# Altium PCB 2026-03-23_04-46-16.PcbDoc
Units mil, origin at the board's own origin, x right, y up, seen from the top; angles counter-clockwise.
Board outline 4000 x 3500 mil, 4 copper layers (Top Layer, MidLayer1, MidLayer2, Bottom Layer); 141 components, 66 nets, 354 pads, 301 vias.
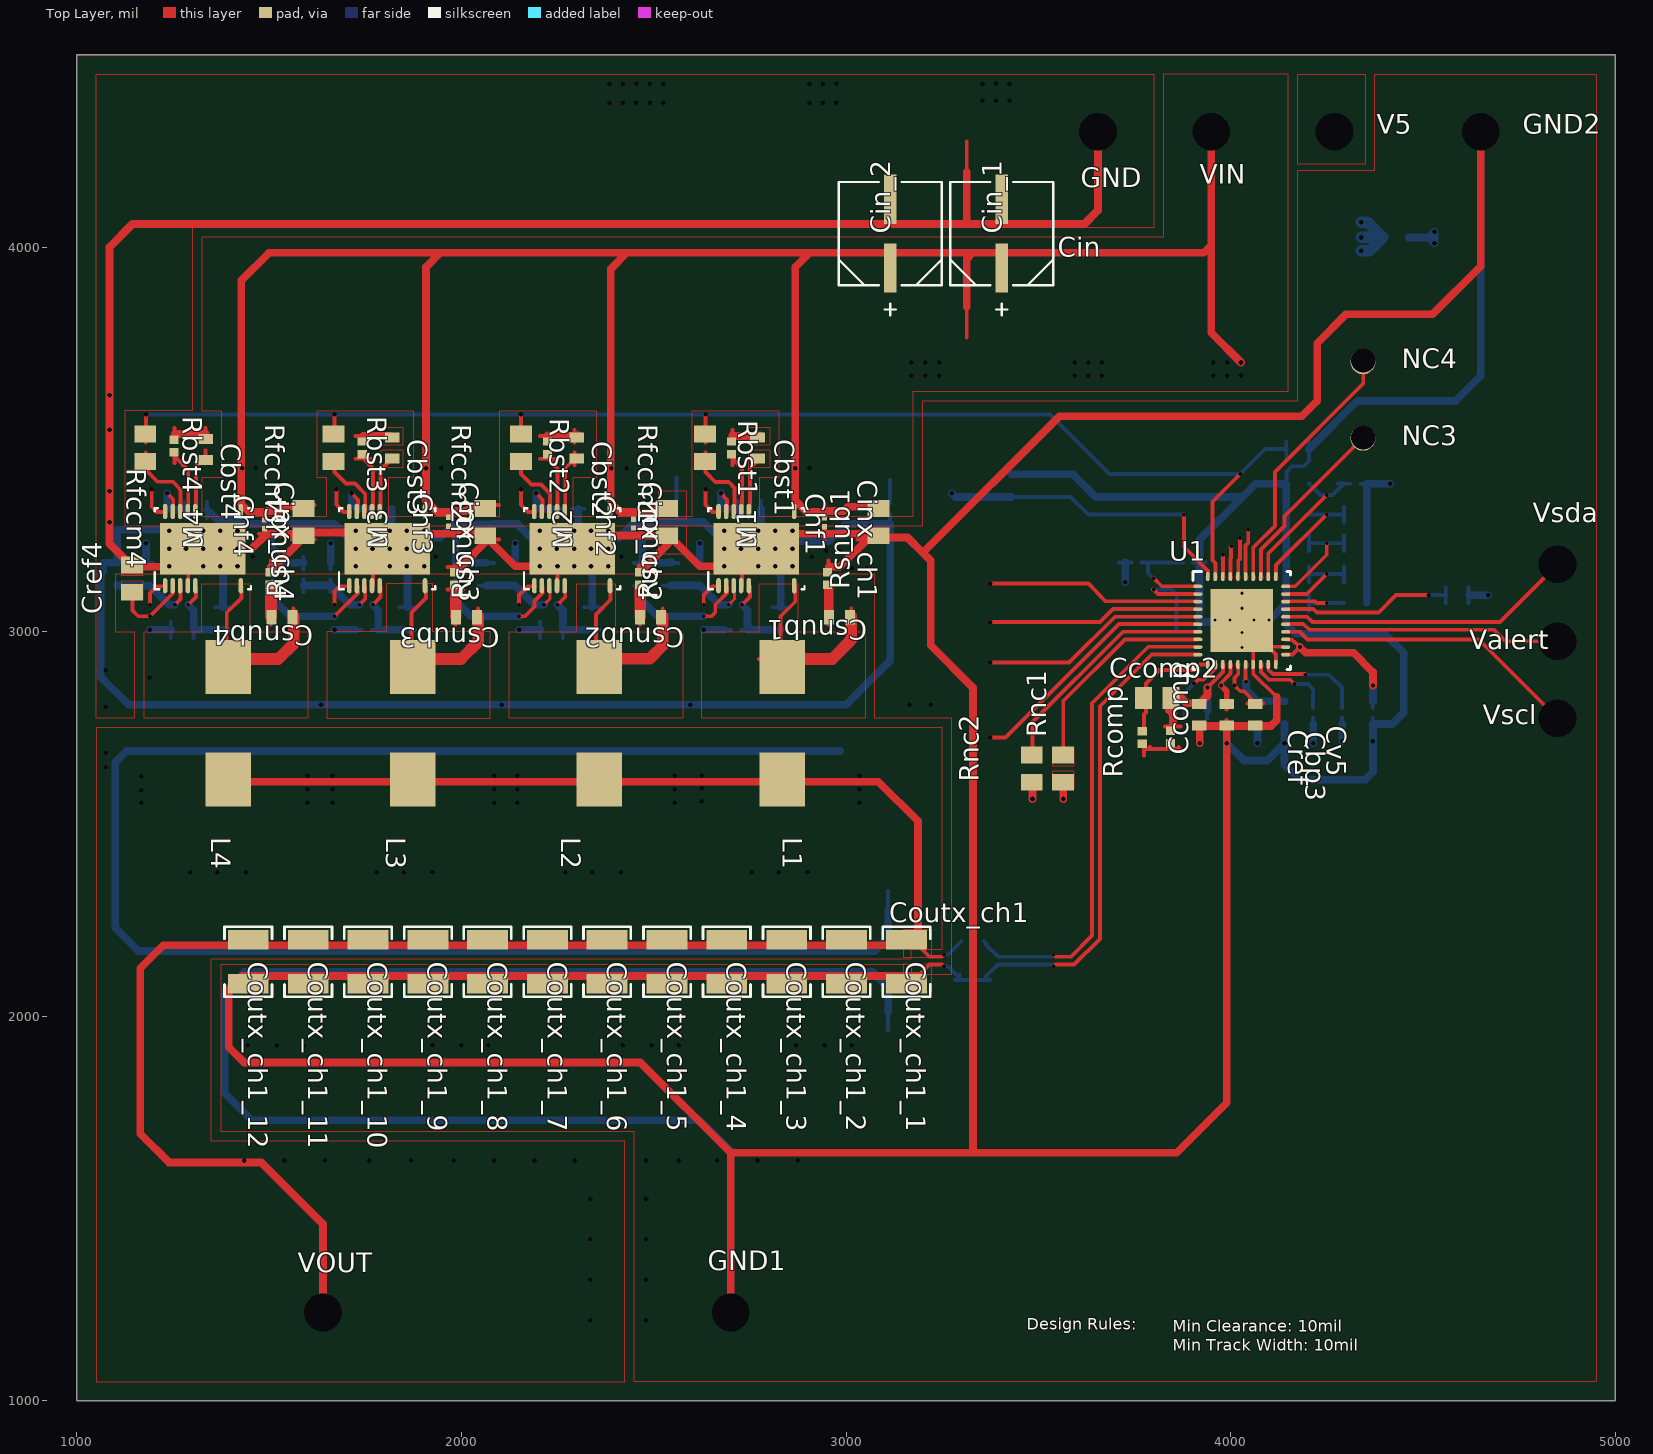
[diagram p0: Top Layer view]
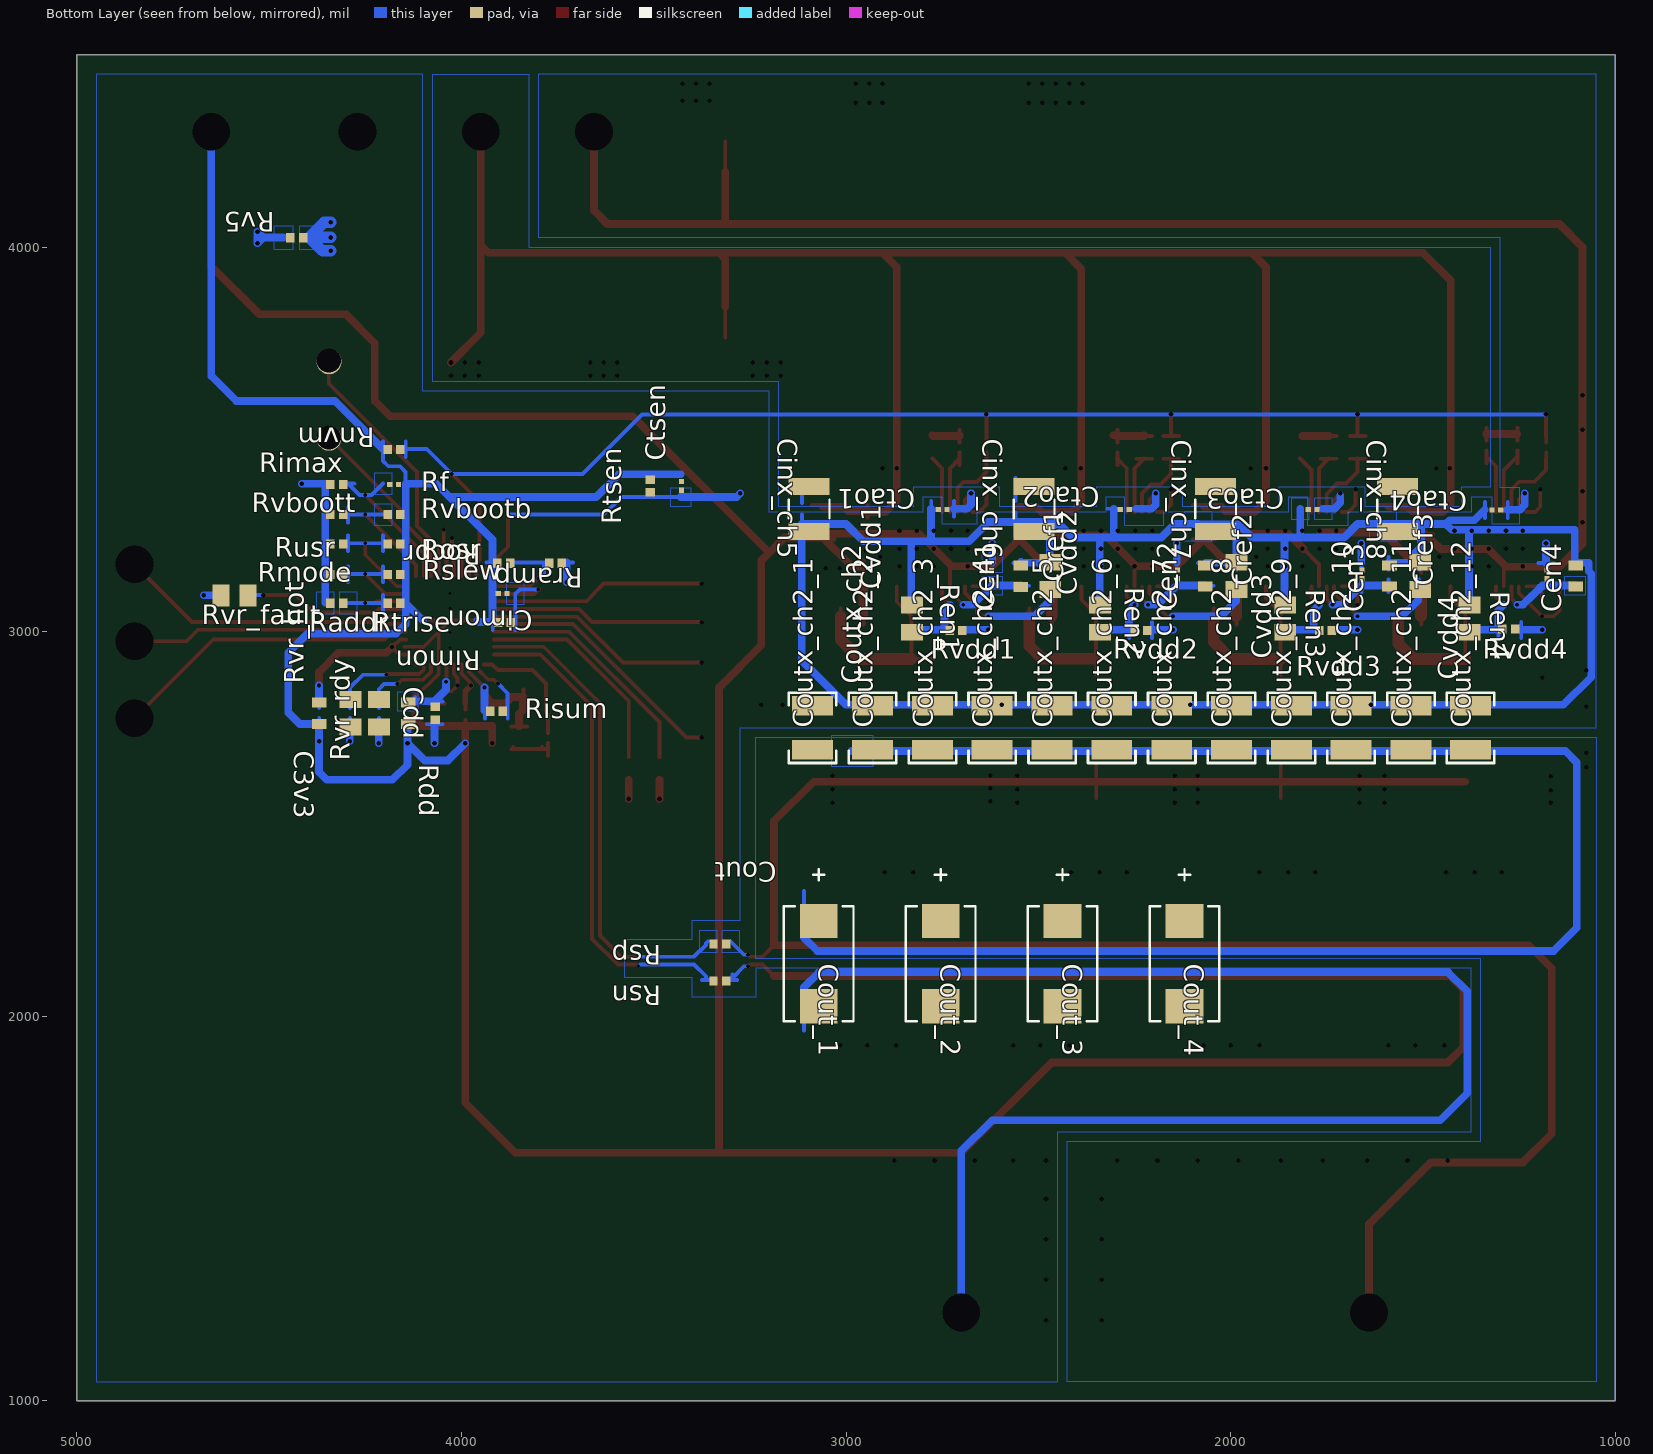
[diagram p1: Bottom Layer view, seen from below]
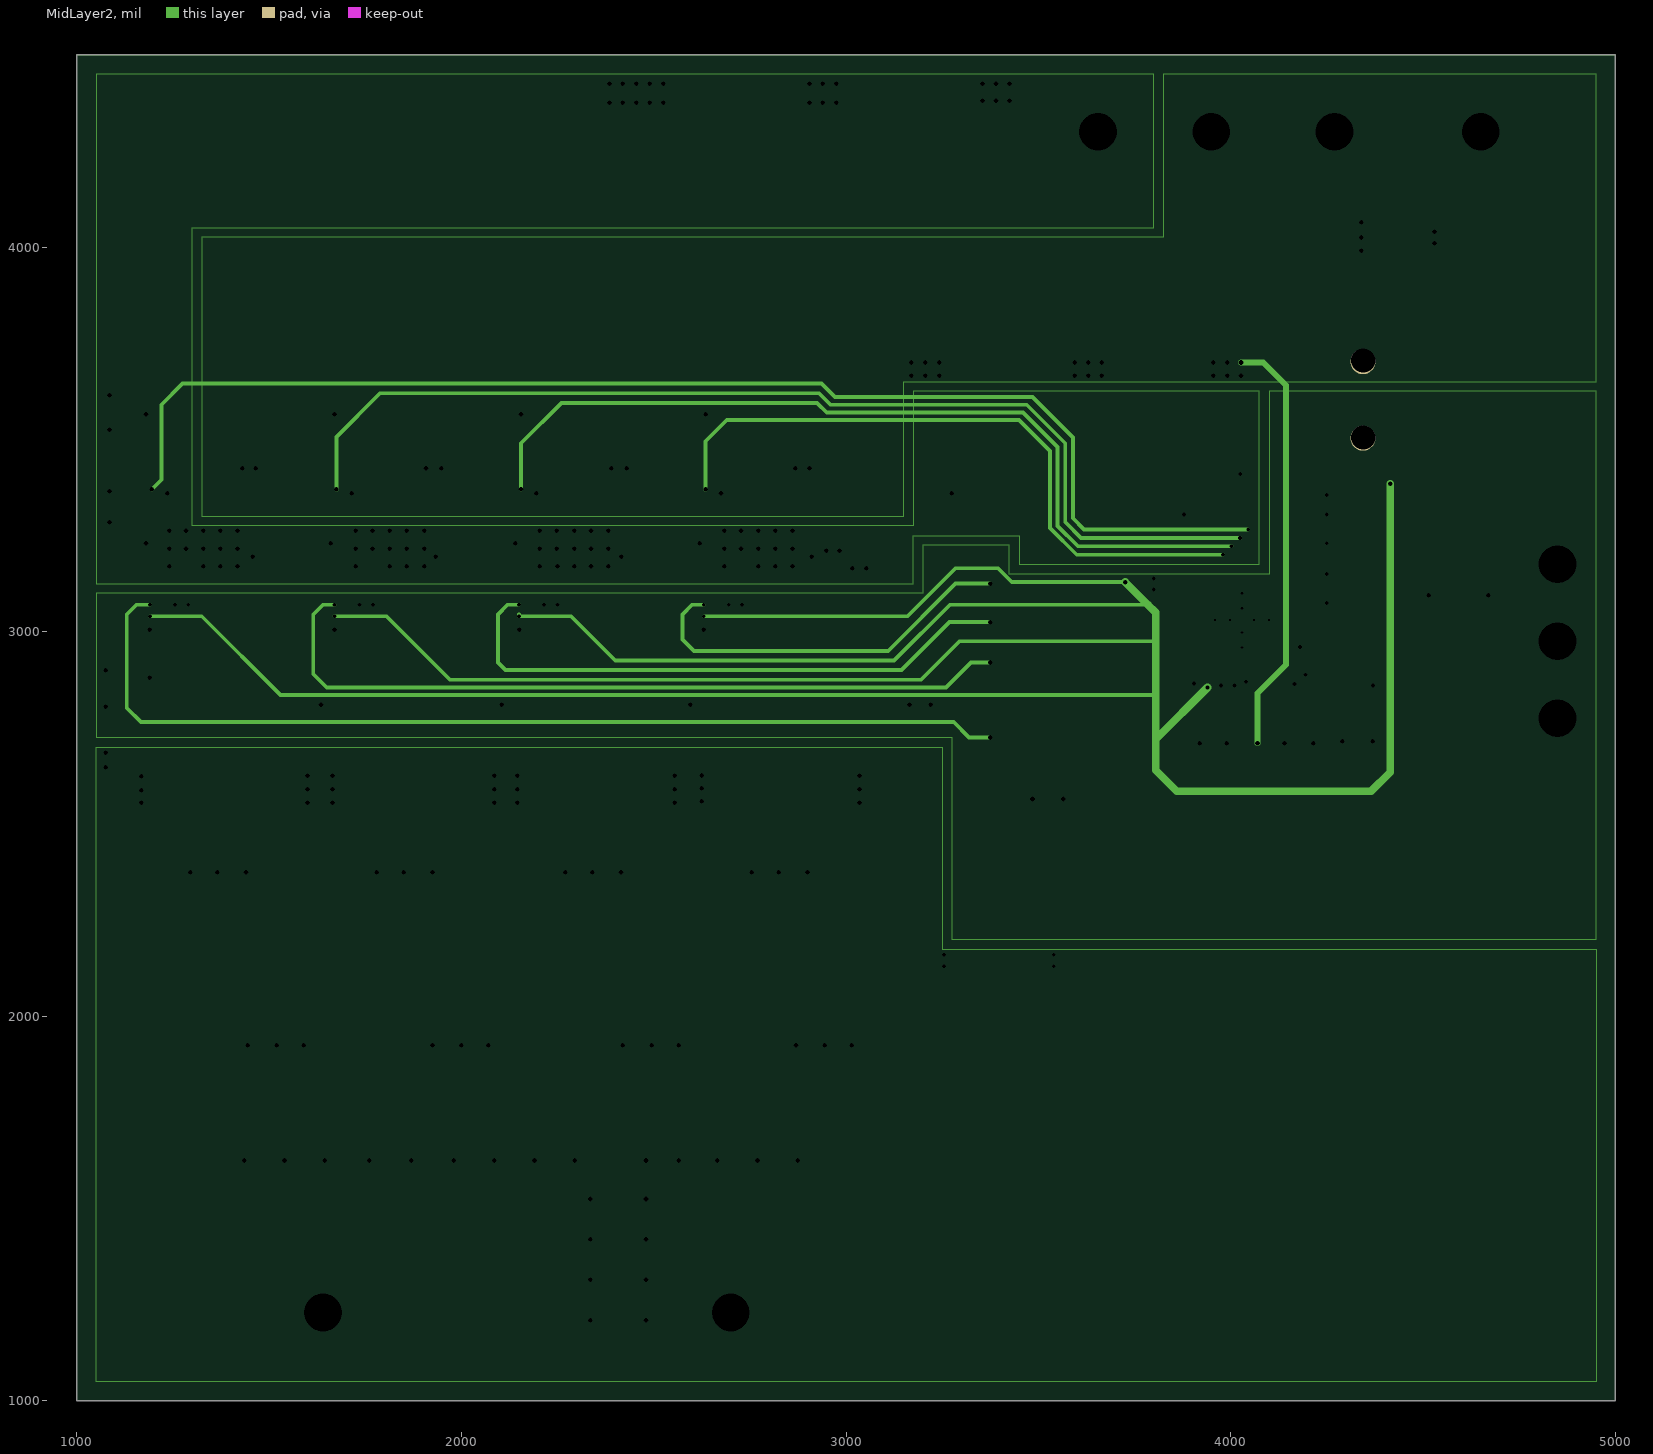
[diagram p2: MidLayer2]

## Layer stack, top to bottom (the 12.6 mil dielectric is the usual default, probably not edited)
Top Layer: signal copper 1.4
Dielectric: core 12.6, FR-4, Dk 4.8
MidLayer1: signal copper 1.4
Dielectric: prepreg 12.6, FR-4, Dk 4.8
MidLayer2: signal copper 1.4
Dielectric: core 12.6, FR-4, Dk 4.8
Bottom Layer: signal copper 1.4

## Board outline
1000,1000 5000,1000 5000,4500 1000,4500

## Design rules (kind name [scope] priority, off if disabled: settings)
PlaneConnect [All] p0: scope1count=1 scope1_0_kind=Board scope1_0_value=Board scope2count=1 scope2_0_kind=Board scope2_0_value=Board commentlength=0 planeconnectstyle=Direct reliefexpansion=20 reliefentries=4 reliefconductorwidth=10 reliefairgap=10
PlaneConnect [All] p1: planeconnectstyle=Direct reliefexpansion=20 reliefentries=4 reliefconductorwidth=10 reliefairgap=10
PolygonConnect [All] p0: scope1count=1 scope1_0_kind=Board scope1_0_value=Board scope2count=1 scope2_0_kind=Board scope2_0_value=Board commentlength=0 connectstyle=Direct reliefconductorwidth=10 reliefentries=4 polygonreliefangle="90 Angle"
PolygonConnect [All] p1: connectstyle=Direct reliefconductorwidth=10 reliefentries=4 polygonreliefangle="90 Angle"

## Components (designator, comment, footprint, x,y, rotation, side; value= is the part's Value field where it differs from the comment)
C3v3 "" 0603#1 4370,2788 r90 bottom
Cbp3 "" 0603#2 3990,2784 r270 top
Cbst1 "" 0603#2 2770,3478 r270 top
Cbst2 "" 0603#2 2300,3478 r270 top
Cbst3 "" 0603#2 1820,3478 r270 top
Cbst4 "" 0603#2 1335,3474 r270 top
Ccomp "" 0402#1 3844,2726 r90 top
Ccomp2 "" 0805#1 3809,2828 r0 top
Cdd "" 0603#1 4138,2788 r90 bottom
Cen1 "" 0603#1 2546,3144 r270 bottom
Cen2 "" 0603#1 2066,3145 r270 bottom
Cen3 "" 0603#1 1587,3145 r270 bottom
Cen4 "" 0603#1 1103,3145 r270 bottom
Chf1 "" 0201_033 2944,3284 r270 top
Chf2 "" 0201_033 2448,3281 r270 top
Chf3 "" 0201_033 1967,3286 r270 top
Chf4 "" 0201_033 1488,3279 r270 top
Cimon "" 0201 3893,3099 r180 bottom
Cin_1 "" CAPSMT_62_C10 3405,4035 r90 top
Cin_2 "" CAPSMT_62_C10 3115,4035 r90 top
Cinx_ch1 "" 0805#1 3084,3285 r270 top
Cinx_ch2 "" 0805#1 2535,3285 r270 top
Cinx_ch3 "" 0805#1 2062,3285 r270 top
Cinx_ch4 "" 0805#1 1590,3285 r270 top
Cinx_ch5 "" 1210_280 3096,3319 r90 bottom
Cinx_ch6 "" 1210_280 2511,3319 r90 bottom
Cinx_ch7 "" 1210_280 2039,3319 r90 bottom
Cinx_ch8 "" 1210_280 1566,3319 r90 bottom
Cout_1 "" 7343-20 3071,2137 r90 bottom
Cout_2 "" 7343-20 2754,2137 r90 bottom
Cout_3 "" 7343-20 2437,2137 r90 bottom
Cout_4 "" 7343-20 2120,2137 r90 bottom
Coutx_ch1_1 "" 1210_270#1 3157,2142 r270 top
Coutx_ch1_2 "" 1210_270#1 3001,2142 r270 top
Coutx_ch1_3 "" 1210_270#1 2846,2142 r270 top
Coutx_ch1_4 "" 1210_270#1 2690,2142 r270 top
Coutx_ch1_5 "" 1210_270#1 2535,2142 r270 top
Coutx_ch1_6 "" 1210_270#1 2379,2142 r270 top
Coutx_ch1_7 "" 1210_270#1 2224,2142 r270 top
Coutx_ch1_8 "" 1210_270#1 2068,2142 r270 top
Coutx_ch1_9 "" 1210_270#1 1913,2142 r270 top
Coutx_ch1_10 "" 1210_270#1 1757,2142 r270 top
Coutx_ch1_11 "" 1210_270#1 1602,2142 r270 top
Coutx_ch1_12 "" 1210_270#1 1446,2142 r270 top
Coutx_ch2_1 "" 1210_270#2 3087,2750 r270 bottom
Coutx_ch2_2 "" 1210_270#2 2931,2750 r270 bottom
Coutx_ch2_3 "" 1210_270#2 2775,2750 r270 bottom
Coutx_ch2_4 "" 1210_270#2 2620,2750 r270 bottom
Coutx_ch2_5 "" 1210_270#2 2464,2750 r270 bottom
Coutx_ch2_6 "" 1210_270#2 2309,2750 r270 bottom
Coutx_ch2_7 "" 1210_270#2 2153,2750 r270 bottom
Coutx_ch2_8 "" 1210_270#2 1998,2750 r270 bottom
Coutx_ch2_9 "" 1210_270#2 1842,2750 r270 bottom
Coutx_ch2_10 "" 1210_270#2 1687,2750 r270 bottom
Coutx_ch2_11 "" 1210_270#2 1531,2750 r270 bottom
Coutx_ch2_12 "" 1210_270#2 1376,2750 r270 bottom
Cref "" 0603#2 3918,2784 r270 top
Cref1 "" 0805#2 2469,3145 r270 bottom
Cref2 "" 0805#2 1985,3145 r270 bottom
Cref3 "" 0805#2 1507,3145 r270 bottom
Cref4 "" 0805#1 1144,3138 r90 top
Csnub1 "" 0603#2 2983,3038 r180 top
Csnub2 "" 0603#2 2492,3038 r180 top
Csnub3 "" 0603#2 2013,3038 r180 top
Csnub4 "" 0603#2 1534,3038 r180 top
Ctao1 "" 0201 2749,3318 r180 bottom
Ctao2 "" 0201 2275,3318 r180 bottom
Ctao3 "" 0201 1787,3318 r180 bottom
Ctao4 "" 0201 1309,3316 r180 bottom
Ctsen "" 0201 3428,3379 r270 bottom
Cv5 "" 0603#2 4064,2784 r270 top
Cvdd1 "" 0805#2 2828,3034 r270 bottom
Cvdd2 "" 0805#2 2340,3034 r270 bottom
Cvdd3 "" 0805#2 1858,3034 r270 bottom
Cvdd4 "" 0805#2 1379,3034 r270 bottom
GND "" TP-1502 3655,4298 r0 top
GND1 "" TP-1502 2698,1228 r0 top
GND2 "" TP-1502 4649,4298 r0 top
L1 "" WE-HCM_1088 2834,2762 r270 top
L2 "" WE-HCM_1088 2359,2762 r270 top
L3 "" WE-HCM_1088 1874,2762 r270 top
L4 "" WE-HCM_1088 1394,2762 r270 top
M1 "" DQP0012A 2767,3216 r90 top
M2 "" DQP0012A 2288,3216 r90 top
M3 "" DQP0012A 1807,3216 r90 top
M4 "" DQP0012A 1328,3216 r90 top
NC3 "" TP-5012 4344,3503 r0 top
NC4 "" TP-5012 4344,3702 r0 top
Raddr "" 0402#2 4324,3074 r0 bottom
Rbst1 "" 0402#1 2702,3478 r270 top
Rbst2 "" 0402#1 2224,3478 r270 top
Rbst3 "" 0402#1 1742,3478 r270 top
Rbst4 "" 0402#1 1253,3483 r270 top
Rcomp "" 0402#1 3770,2725 r90 top
Rdd "" 0402#2 4068,2788 r90 bottom
Ren1 "" 0201 2622,3147 r90 bottom
Ren2 "" 0201 2138,3149 r90 bottom
Ren3 "" 0201 1659,3149 r90 bottom
Ren4 "" 0201 1178,3149 r90 bottom
Rf "" 0201 4175,3383 r0 bottom
Rfccm1 "" 0805#1 2633,3478 r270 top
Rfccm2 "" 0805#1 2155,3478 r270 top
Rfccm3 "" 0805#1 1668,3478 r270 top
Rfccm4 "" 0805#1 1178,3478 r270 top
Rimax "" 0402#2 4324,3383 r0 bottom
Rimon "" 0402#2 3888,3024 r180 bottom
Risum "" 0402#2 3909,2793 r0 bottom
Rmode "" 0402#2 4324,3149 r0 bottom
Rnc1 "" 0805#1 3564,2644 r90 top
Rnc2 "" 0805#1 3483,2644 r90 top
Rnvm "" 0402#2 4175,3474 r180 bottom
Rocpr "" 0402#2 3890,3178 r180 bottom
Rosr "" 0402#2 4175,3228 r0 bottom
Rramp "" 0402#2 3755,3178 r180 bottom
Rslew "" 0402#2 4175,3149 r0 bottom
Rsn "" 0402#2 3328,2092 r180 bottom
Rsnub1 "" 0402#1 2952,3138 r90 top
Rsnub2 "" 0402#1 2464,3138 r90 top
Rsnub3 "" 0402#1 1983,3138 r90 top
Rsnub4 "" 0402#1 1503,3138 r90 top
Rsp "" 0402#2 3328,2188 r180 bottom
Rtrise "" 0402#2 4175,3074 r0 bottom
Rtsen "" 0402#2 3509,3379 r270 bottom
Rusr "" 0402#2 4324,3228 r0 bottom
Rv5 "" 0402#2 4428,4024 r180 bottom
Rvbootb "" 0402#2 4175,3305 r0 bottom
Rvboott "" 0402#2 4324,3305 r0 bottom
Rvdd1 "" 0402#2 2714,3003 r0 bottom
Rvdd2 "" 0402#2 2233,3003 r0 bottom
Rvdd3 "" 0402#2 1753,3003 r0 bottom
Rvdd4 "" 0402#2 1277,3007 r0 bottom
Rvr_fault "" 0805#2 4590,3094 r0 bottom
Rvr_hot "" 0805#2 4288,2788 r270 bottom
Rvr_rdy "" 0805#2 4214,2788 r270 bottom
U1 "" RTA0040B 4029,3029 r0 top
V5 "" TP-1502 4269,4298 r0 top
Valert "" TP-1502 4849,2974 r0 top
VIN "" TP-1502 3948,4298 r0 top
VOUT "" TP-1502 1638,1228 r0 top
Vscl "" TP-1502 4849,2775 r0 top
Vsda "" TP-1502 4849,3175 r0 top

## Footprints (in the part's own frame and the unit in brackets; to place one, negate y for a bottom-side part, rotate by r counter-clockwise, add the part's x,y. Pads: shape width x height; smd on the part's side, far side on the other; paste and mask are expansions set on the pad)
0201 [mil]
  rect 14x13 smd: 1(11.5,0) 2(-11.5,0)
0201_033 [mil]
  rect 14x13 smd: 1(-11.5,0) 2(11.5,0)
0402#1 [mil]
  rect 22x24 smd: 1(-16.5,0) 2(16.5,0)
0402#2 [mil]
  rect 22x24 smd: 1(16.5,0) 2(-16.5,0)
0603#1 [mil]
  rect 26x38 smd: 1(27.5,0) 2(-27.5,0)
0603#2 [mil]
  rect 26x38 smd: 1(-27.5,0) 2(27.5,0)
0805#1 [mil]
  rect 44x57 smd: 1(-35.5,0) 2(35.5,0)
0805#2 [mil]
  rect 44x57 smd: 1(35.5,0) 2(-35.5,0)
1210_270#1 [mm]
  rect 1.3x2.7 smd: 1(-1.45,0) 2(1.45,0)
  silkscreen extent -2.32,-1.57 2.32,1.57
1210_270#2 [mm]
  rect 1.3x2.7 smd: 1(1.45,0) 2(-1.45,0)
  silkscreen extent -2.32,-1.57 2.32,1.57
1210_280 [mil]
  rect 44x106 smd: 1(59,0) 2(-59,0)
  silkscreen extent -24,-53 24,53
7343-20 [mil]
  rect 89x98 smd: 1(111,0) 2(-111,0)
  silkscreen extent -150,-91 246,91
CAPSMT_62_C10 [mil]
  rect 128x32 smd: 1(-89.5,0) 2(89.5,0)
  silkscreen extent -212,-134 134,134
DQP0012A [mm]
  oval 1x0.3 smd: 1(-2.45,2.501) 2(-2.45,2.001) 3(-2.45,1.5) 4(-2.45,1) 5(-2.45,0.5) 6(-2.45,-2.501) 7(2.45,-2.501) 8(2.45,0.5) 9(2.45,1) 10(2.45,1.5) 11(2.45,2.001) 12(2.45,2.501)
  rect 3.4x5.639 smd: 13(0,0)
  silkscreen extent -2.68,-3.17 2.68,3.17
RTA0040B [mm]
  oval 0.6x0.23 smd: 1(-2.9,2.25) 2(-2.9,1.75) 3(-2.9,1.25) 4(-2.9,0.75) 5(-2.9,0.25) 6(-2.9,-0.25) 7(-2.9,-0.75) 8(-2.9,-1.25) 9(-2.9,-1.75) 10(-2.9,-2.25) 21(2.9,-2.25) 22(2.9,-1.75) 23(2.9,-1.25) 24(2.9,-0.75) 25(2.9,-0.25) 26(2.9,0.25) 27(2.9,0.75) 28(2.9,1.25) 29(2.9,1.75) 30(2.9,2.25)
  oval 0.23x0.6 smd: 11(-2.25,-2.9) 12(-1.75,-2.9) 13(-1.25,-2.9) 14(-0.75,-2.9) 15(-0.25,-2.9) 16(0.25,-2.9) 17(0.75,-2.9) 18(1.25,-2.9) 19(1.75,-2.9) 20(2.25,-2.9) 31(2.25,2.9) 32(1.75,2.9) 33(1.25,2.9) 34(0.75,2.9) 35(0.25,2.9) 36(-0.25,2.9) 37(-0.75,2.9) 38(-1.25,2.9) 39(-1.75,2.9) 40(-2.25,2.9)
  rect 4.15x4.15 smd: 41(0,0)
  silkscreen extent -3.22,-3.22 3.22,3.22
TP-1502 [mil]
  round 65 hole 32: 1(0,0)
TP-5012 [mil]
  round 65 hole 32: 1(0,0)
WE-HCM_1088 [mm]
  rect 3.56x3 smd: 1(-3.71,0) 2(3.71,0)

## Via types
v1: diameter 0, hole 12, Top Layer to Bottom Layer, 240 vias
v2: diameter 0, hole 10, Top Layer to Bottom Layer, 42 vias
v3: diameter 0, hole 98, Top Layer to Bottom Layer, 9 vias
v4: diameter 0, hole 8, Top Layer to Bottom Layer, 8 vias
v5: diameter 0, hole 63, Top Layer to Bottom Layer, 2 vias

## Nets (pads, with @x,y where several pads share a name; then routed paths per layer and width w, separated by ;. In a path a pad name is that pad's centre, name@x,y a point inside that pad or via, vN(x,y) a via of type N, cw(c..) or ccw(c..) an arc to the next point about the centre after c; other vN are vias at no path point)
0: C3v3.2 Cbp3.2 Cdd.2 Cen1.2 Cen2.2 Cen3.2 Cen4.2 Chf1.2 Chf2.2 Chf3.2 Chf4.2 Cimon.2 Cin_1.2 Cin_2.2 Cinx_ch1.2 Cinx_ch2.2 Cinx_ch3.2 Cinx_ch4.2 Cinx_ch5.2 Cinx_ch6.2 Cinx_ch7.2 Cinx_ch8.2 Cout_1.2 Cout_2.2 Cout_3.2 Cout_4.2 Coutx_ch1_1.2 Coutx_ch1_2.2 Coutx_ch1_3.2 Coutx_ch1_4.2 Coutx_ch1_5.2 Coutx_ch1_6.2 Coutx_ch1_7.2 Coutx_ch1_8.2 Coutx_ch1_9.2 Coutx_ch1_10.2 Coutx_ch1_11.2 Coutx_ch1_12.2 Coutx_ch2_1.2 Coutx_ch2_2.2 Coutx_ch2_3.2 Coutx_ch2_4.2 Coutx_ch2_5.2 Coutx_ch2_6.2 Coutx_ch2_7.2 Coutx_ch2_8.2 Coutx_ch2_9.2 Coutx_ch2_10.2 Coutx_ch2_11.2 Coutx_ch2_12.2 Cref1.2 Cref2.2 Cref3.2 Cref4.2 Cref.2 Ctao1.2 Ctao2.2 Ctao3.2 Ctao4.2 Ctsen.2 Cv5.2 Cvdd1.2 Cvdd2.2 Cvdd3.2 Cvdd4.2 GND1.1 GND2.1 GND.1 M1.4 M1.13 M2.4 M2.13 M3.4 M3.13 M4.4 M4.13 Rf.2 Rimon.2 Rnvm.2 Rocpr.2 Rosr.2 Rslew.2 Rsn.1 Rsnub1.2 Rsnub2.2 Rsnub3.2 Rsnub4.2 Rtrise.2 Rtsen.2 Rvbootb.2 U1.17 U1.20 U1.22 U1.41 | length 34184.2
  Top Layer w10: M4.4@1290,3118 M4.13@1290,3175 ; 1474,3254.5 1515,3254.5 ; Rsnub4.2@1504.5,3152 1504.5,3185 ; 1560,3239.5 Cinx_ch4.2@1618,3239.5 ; M3.4@1770,3118 1770,3175 M3.13@1810,3215 ; 1959,3254.5 2000,3254.5 ; 1964,3168.5 2005,3168.5 ; Cinx_ch3.2@2040,3239.5 2098,3239.5 ; M2.4@2250,3118 M2.13@2250,3158 ; 2439,3249.5 2480,3249.5 ; M1.4@2730,3118 M1.13@2730,3175 ; 2944.5,3238 Chf1.2@2944.5,3271 ; Rsnub1.2@2954.5,3152 2954.5,3185 ; 3030,3239.5 Cinx_ch1.2@3088,3239.5 ; Coutx_ch1_1.2@3187,2105 3217,2135 3250,2135 v2(3255,2130) ; 3314,4116 3314,4275 ; U1.41@3955,3029.5 U1.41@4104,3029.5 ; 3989.5,2738 3989.5,2771 ; U1.41@4030,3030 U1.41@4059,3000 ; 4044,2754.5 4085,2754.5 ; U1.20@4118,2915 4118,2941 U1.41@4098,2961 ; 4120,2830 4059,2890 4059,2915 U1.41@4059,3000 ; U1.22@4148,2961 U1.41@4098,2961 ; U1.41@4059,3000 U1.41@4098,2961
  Top Layer w20: 1505,3169 1514,3169 Cinx_ch4.2@1590,3245 ; M3.13@1767,3258 1603,3258 Cinx_ch4.2@1590,3245 ; M3.13@1810,3215 1850,3255 1980,3255 2054,3255 Cinx_ch3.2@2070,3240 ; 1985,3169 1999,3169 Cinx_ch3.2@2070,3240 ; 2465,3169 2479,3169 Cinx_ch2.2@2550,3240 ; v3(2700,1230) 2700,1645 ; 2955,3169 2984,3169 Cinx_ch1.2@3060,3245 ; Coutx_ch1_1.2@3187,2105 1430,2105 1395,2070 1395,1920 1435,1880 2465,1880 2700,1645 ; 3314,4195 3314,4060 ; v3(3655,4300) 3655,4095 3620,4060 3315,4060 3314,4060 ; v1(3920,2710) 3920,2755 Cbp3.2@3990,2755 ; 4120,2830 4120,2770 4105,2755 4065,2755 Cbp3.2@3990,2755 ; v3(4650,4300) 4650,3950 4525,3825 4300,3825 4225,3750 4225,3600 4185,3560 3555,3560 3200,3205 ; Cinx_ch4.2@1590,3245 1579,3255 1495,3255 1454,3215 1330,3215 1290,3175 1284,3169 1145,3169 1085,3229 v1(1085,3615) 1085,4000 1145,4060 3314,4060 ; Cinx_ch3.2@2070,3240 2140,3170 2245,3170 2325,3250 2460,3250 2539,3250 Cinx_ch2.2@2550,3240 ; Cinx_ch2.2@2550,3240 2620,3170 2725,3170 2730,3175 2810,3255 2945,3255 3049,3255 Cinx_ch1.2@3060,3245 ; 2700,1645 3330,1645 ; Cinx_ch1.2@3060,3245 3160,3245 3200,3205 ; 3200,3205 3220,3185 3220,2965 3330,2855 3330,1645 ; 3330,1645 3860,1645 3990,1775 v1(3990,2710) Cbp3.2@3990,2755
  Bottom Layer w10: 1338.5,3296 1338.5,3337 ; Cvdd4.2@1359,3063.5 Cvdd4.2@1400,3063.5 ; Cref3.2@1509.5,3162 Cref3.2@1509.5,3195 ; Cen3.2@1589.5,3162 1589.5,3195 ; Cvdd3.2@1839,3063.5 Cvdd3.2@1880,3063.5 ; Cref2.2@1984.5,3162 Cref2.2@1984.5,3195 ; 2044,3178.5 2085,3178.5 ; Ctao2.2@2287,3319.5 2320,3319.5 ; Cvdd2.2@2319,3063.5 Cvdd2.2@2360,3063.5 ; Cref1.2@2449,3178.5 Cref1.2@2490,3178.5 ; 2524,3178.5 2565,3178.5 ; Cinx_ch6.2@2559,3249 2559,3310 ; 2778.5,3299 2778.5,3340 ; Cvdd1.2@2809,3063.5 Cvdd1.2@2850,3063.5 ; 3109,1963 Cout_1.2@3109,2059 ; Cinx_ch5.2@3114,3244 3114,3305 ; v2(3255,2130) 3265,2130 3295,2100 ; 3283,2094.5 Rsn.1@3316,2094.5 ; 3295,2109 3295,2100 ; 3300,2095 3295,2100 ; 3489,3408.5 3530,3408.5 ; Rocpr.2@3902,3179.5 3935,3179.5 ; 3918.5,3004 3918.5,3045 ; 3919,3050 3919,3100 ; 4144.5,3054 4144.5,3095 ; 4144.5,3129 4144.5,3170 ; 4144.5,3209 4144.5,3250 ; 4145,3385 4145,3415 4160,3430 4190,3430 4204,3444 4204,3475 ; 4203.5,3454 4203.5,3495 ; 4369.5,2743 4369.5,2776
  Bottom Layer w20: 1339,3317 1367,3290 1430,3290 1440,3280 ; Cvdd4.2@1380,3064 1380,3258 ; Cen3.2@1590,3179 1520,3179 1520,3205 1505,3220 1505,3280 ; 1819,3320 1819,3245 ; Cvdd3.2@1860,3064 1860,3245 ; Cen2.2@2065,3179 1985,3179 1985,3274 1980,3279 ; 2304,3320 2304,3245 2305,3245 ; Cvdd2.2@2340,3064 2340,3245 ; Cen1.2@2544,3180 Cen1.2@2545,3181 ; Cen1.2@2545,3179 2470,3179 2470,3265 2450,3285 ; v3(2700,1230) 2700,1650 2620,1730 1455,1730 1385,1800 1385,2065 1435,2115 3070,2115 3110,2075 Cout_1.2@3110,2011 ; 2779,3320 2779,3235 2780,3235 ; Cvdd1.2@2830,3064 2830,3235 ; 3430,3409 3510,3409 3590,3409 3650,3350 4030,3350 ; v4(3959,3030) 3954,3025 3919,3025 3919,3050 3919,3115 3919,3180 3919,3239 4030,3350 ; v1(3990,2710) 4035,2665 4095,2665 v1(4140,2710) ; v4(4100,3030) 4145,3074 ; Cdd.2@4140,2760 v1(4140,2710) ; 4204,3475 4329,3600 4585,3600 4650,3665 v3(4650,4300) ; 1440,3280 1425,3265 1105,3265 1105,3179 1069,3179 1069,3157 1062,3150 1062,2882 1135,2810 2985,2810 3000,2810 3115,2925 3115,3280 3000,3280 2955,3235 2830,3235 ; 1440,3280 1505,3280 ; 1505,3280 1605,3280 1670,3280 1705,3245 1819,3245 ; 1819,3245 1860,3245 ; 1860,3245 1945,3245 1980,3279 ; 1980,3279 2084,3279 2085,3280 2145,3280 2180,3245 2305,3245 ; 2305,3245 2340,3245 ; 2340,3245 2410,3245 2450,3285 ; 2450,3285 2560,3285 2630,3285 2680,3235 2780,3235 ; 2780,3235 2830,3235 ; 4030,3350 4065,3385 4145,3385 4145,3305 4145,3230 4145,3150 4145,3075 4145,3074 ; v1(4140,2710) 4140,2654 4180,2615 4350,2615 4370,2635 4370,2760 4420,2760 4450,2790 4450,2945 4400,2995 4170,2995 4145,3019 4145,3074
  other v1: 2480,1210 2480,1315 2480,1420 2480,1525 2480,1625 2565,1625 2665,1625 2770,1625 2875,1625 1445,1925 1520,1925 1590,1925 1925,1925 2000,1925 2070,1925 2420,1925 2495,1925 2565,1925 2870,1925 2945,1925 3015,1925 4370,2715 1075,2805 1635,2810 2105,2810 2595,2810 3165,2810 3220,2810 1190,2880 1075,2900 3016,3165 3053,3165 1240,3170 1329,3170 1373,3170 1418,3170 1725,3170 1814,3170 1858,3170 1903,3170 2204,3170 2250,3170 2293,3170 2337,3170 2382,3170 2683,3170 2772,3170 2816,3170 2861,3170 1458,3195 1933,3195 2416,3195 2911,3195 2949,3210 2983,3210 1240,3216 1284,3216 1329,3216 1373,3216 1418,3216 1725,3216 1769,3216 1814,3216 1858,3216 1903,3216 2204,3216 2248,3216 2293,3216 2337,3216 2382,3216 2683,3216 2727,3216 2772,3216 2816,3216 2861,3216 1240,3262 1284,3262 1329,3262 1373,3262 1418,3262 1725,3262 1769,3262 1814,3262 1858,3262 1903,3262 2204,3262 2248,3262 2293,3262 2337,3262 2382,3262 2683,3262 2727,3262 2772,3262 2816,3262 2861,3262 1085,3285 1085,3365 1085,3525 2385,4375 2420,4375 2455,4375 2490,4375 2525,4375 2905,4375 2940,4375 2975,4375 3355,4380 3390,4380 3425,4380 2385,4425 2420,4425 2455,4425 2490,4425 2525,4425 2905,4425 2940,4425 2975,4425 3355,4425 3390,4425 3425,4425
  other v4: 4030,2959 4030,2998 3998,3030 4061,3030 4030,3061 4030,3100
1: Chf1.1 Chf2.1 Chf3.1 Chf4.1 Cin_1.1 Cin_2.1 Cinx_ch1.1 Cinx_ch2.1 Cinx_ch3.1 Cinx_ch4.1 Cinx_ch5.1 Cinx_ch6.1 Cinx_ch7.1 Cinx_ch8.1 M1.7 M2.7 M3.7 M4.7 Rdd.2 VIN.1 | length 8456.4
  Top Layer w10: 1474,3313.5 1515,3313.5 ; 1560,3329.5 Cinx_ch4.1@1618,3329.5 ; 1959,3313.5 2000,3313.5 ; Cinx_ch3.1@2040,3329.5 2098,3329.5 ; 2439,3308.5 2480,3308.5 ; Chf1.1@2944.5,3297 2944.5,3330 ; 3030,3329.5 Cinx_ch1.1@3088,3329.5 ; 3314,3765 3314,3924
  Top Layer w20: Cinx_ch4.1@1590,3325 1540,3325 1529,3314 1495,3314 1491,3311 1448,3311 1428,3331 1428,3913 1500,3985 1945,3985 ; Cinx_ch3.1@2070,3325 2025,3325 2014,3314 1980,3314 1976,3311 1938,3311 1908,3341 1908,3948 1945,3985 ; Cinx_ch2.1@2550,3325 2505,3325 2489,3309 2460,3309 2458,3311 2413,3311 2388,3336 2388,3943 2430,3985 ; Cinx_ch1.1@3060,3325 3005,3325 2994,3314 2945,3314 2941,3311 2898,3311 2868,3341 2868,3948 2905,3985 ; 3314,3845 3314,3969 3330,3985 ; v3(3950,4300) 3950,4005 ; v1(4027,3700) 3950,3777 3950,4005 ; 1945,3985 2430,3985 ; 2430,3985 2905,3985 ; 2905,3985 3330,3985 ; 3330,3985 3930,3985 3950,4005
  MidLayer2 w15: v1(4027,3700) 4085,3700 4144,3641 4144,2914 4070,2840 v1(4070,2710)
  Bottom Layer w10: 2559,3339 2559,3400 ; 3114,3334 Cinx_ch5.1@3114,3395 ; 4049,2759.5 4090,2759.5
  Bottom Layer w20: v1(4070,2710) 4070,2760
  other v1: 1430,3425 1465,3425 1908,3425 1948,3425 2390,3425 2430,3425 2868,3425 2905,3425 3170,3665 3206,3665 3242,3665 3595,3665 3630,3665 3665,3665 3955,3665 3991,3665 4027,3665 3170,3700 3206,3700 3242,3700 3595,3700 3630,3700 3665,3700 3955,3700 3991,3700
2: Rocpr.1 Rramp.2 U1.1 | length 310.8
  Top Layer w10: v2(3800,3138) 3801,3138 3821,3118 U1.1@3915,3118
  Bottom Layer w10: Rramp.2@3768,3179.5 3801,3179.5 ; v2(3800,3138) 3785,3152 3785,3180 3858,3180 ; 3843,3179.5 Rocpr.1@3876,3179.5
5: Rf.1 Rimax.2 U1.32 | length 437.8
  Top Layer w10: U1.32@4098,3144 4098,3203 v2(4250,3355)
  Bottom Layer w10: 4204,3385 4234,3355 v2(4250,3355) 4265,3355 4295,3385 4280,3385 ; 4278,3384.5 Rimax.2@4311,3384.5
6: Rvbootb.1 Rvboott.2 U1.31 | length 347.7
  Top Layer w10: U1.31@4118,3144 4118,3173 v2(4250,3305)
  Bottom Layer w10: 4204,3305 v2(4250,3305) 4295,3305 ; 4294.5,3284 4294.5,3325
7: Rosr.1 Rusr.2 U1.30 | length 343
  Top Layer w10: U1.30@4144,3118 4168,3118 4250,3200 v2(4250,3230)
  Bottom Layer w10: 4203.5,3209 4203.5,3250 ; 4204,3230 v2(4250,3230) 4295,3230 ; 4294.5,3209 4294.5,3250
9: Rmode.2 Rslew.1 U1.29 | length 300.5
  Top Layer w10: U1.29@4144,3098 4198,3098 v2(4250,3150)
  Bottom Layer w10: 4203.5,3129 4203.5,3170 ; 4204,3150 v2(4250,3150) 4295,3150 ; 4294.5,3129 4294.5,3170
10: Raddr.2 Rtrise.1 U1.28 | length 239.4
  Top Layer w10: U1.28@4144,3079 4220,3079 4225,3075 v2(4250,3075)
  Bottom Layer w10: 4203.5,3054 4203.5,3095 ; 4204,3075 v2(4250,3075) 4295,3075
22: Cdd.1 Rdd.1 U1.16 | length 220.4
  Top Layer w10: U1.16@4039,2915 4039,2870 v2(4040,2870)
  Bottom Layer w10: 4049,2818.5 4090,2818.5
  Bottom Layer w20: v2(4040,2870) 4040,2849 4070,2819 Cdd.1@4140,2819
23: Cv5.1 Rv5.2 U1.15 | length 2292.2
  Top Layer w10: U1.15@4020,2915 4020,2890 4010,2880 v2(4010,2860) 4025,2845 4035,2845 4065,2814 Cv5.1@4075,2814 ; 4044,2813.5 4085,2813.5
  Mid-Layer 5 w10: 4010,2830 v2(4010,2860)
  Mid-Layer 5 w20: 4010,2830 4040,2800 4570,2800 4720,2950 4720,3820 v1(4530,4010) v1(4530,4040)
  Bottom Layer w20: 4463,4025 4515,4025 ; 4515,4025 v1(4530,4010) v1(4530,4040) 4515,4025
24: Rv5.1 Rvdd1.2 Rvdd2.2 Rvdd3.2 Rvdd4.2 V5.1 | length 4763.1
  Mid-Layer 5 w20: v1(1190,3005) v1(1670,3005) v1(2150,3005) v1(2630,3005) 2770,3005 2830,3065 3240,3065 3335,3160 3335,3250 3450,3365 4115,3365 4270,3520 4270,4065 ; v3(4270,4300) 4270,4065 ; v1(4340,4065) 4270,4065
  Bottom Layer w10: 1244.5,2984 1244.5,3025 ; 1708,3004.5 Rvdd3.2@1741,3004.5 ; 2204.5,2984 2204.5,3025 ; 2668,3004.5 Rvdd1.2@2701,3004.5
  Bottom Layer w20: v1(1190,3005) 1245,3005 ; v1(1670,3005) 1725,3005 ; v1(2150,3005) 2205,3005 ; v1(2630,3005) 2685,3005
  Bottom Layer w30: v1(4340,3990) 4361,3990 4396,4025 ; v1(4340,4025) 4396,4025 ; v1(4340,4065) 4356,4065 4396,4025
30: Ccomp2.1 Rcomp.2 U1.11 | length 368.8
  Top Layer w10: Rcomp.2@3774.5,2737 3774.5,2770 ; 3775,2754 3775,2785 3780,2790 3780,2830 3780,2865 3815,2900 3905,2900 3920,2915 U1.11@3941,2915 ; Ccomp2.1@3779.5,2809 Ccomp2.1@3779.5,2850
31: Cimon.1 Rimon.1 U1.2 | length 300.4
  Top Layer w10: 3798,3110 v2(3800,3110) 3811,3098 U1.2@3915,3098
  Bottom Layer w10: v2(3800,3110) 3848,3110 3858,3100 ; 3859.5,3004 3859.5,3045 ; 3860,3025 3860,3100
34: Cvdd4.1 M4.5 Rvdd4.1 | length 284.8
  Top Layer w10: v2(1290,3070) 1310,3090 M4.5@1310,3118
  Bottom Layer w10: 1303.5,2984 1303.5,3025 ; Cvdd4.1@1359,3004.5 Cvdd4.1@1400,3004.5
  Bottom Layer w20: v2(1290,3070) 1304,3055 1304,3005 Cvdd4.1@1380,3005
35: Cvdd3.1 M3.5 Rvdd3.1 | length 276.8
  Top Layer w10: v2(1770,3070) 1790,3090 M3.5@1790,3118
  Bottom Layer w10: Rvdd3.1@1767,3004.5 1800,3004.5 ; Cvdd3.1@1839,3004.5 Cvdd3.1@1880,3004.5
  Bottom Layer w20: v2(1770,3070) 1784,3055 1784,3005 1785,3005 Cvdd3.1@1860,3005
36: Cvdd2.1 M2.5 Rvdd2.1 | length 284.8
  Top Layer w10: v2(2250,3070) 2270,3090 M2.5@2270,3118
  Bottom Layer w10: 2263.5,2984 2263.5,3025 ; Cvdd2.1@2319,3004.5 Cvdd2.1@2360,3004.5
  Bottom Layer w20: v2(2250,3070) 2264,3055 2264,3005 2265,3005 Cvdd2.1@2340,3005
37: Cvdd1.1 M1.5 Rvdd1.1 | length 286.8
  Top Layer w10: v2(2730,3070) 2750,3090 M1.5@2750,3118
  Bottom Layer w10: Rvdd1.1@2727,3004.5 2760,3004.5 ; Cvdd1.1@2809,3004.5 Cvdd1.1@2850,3004.5
  Bottom Layer w20: v2(2730,3070) 2744,3055 2744,3005 2745,3005 Cvdd1.1@2830,3005
38: Cen3.1 M3.3 Ren3.2 | length 285.9
  Top Layer w10: v2(1735,3070) 1750,3085 M3.3@1750,3118
  Bottom Layer w10: 1589.5,3103 1589.5,3136 ; 1659.5,3103 Ren3.2@1659.5,3136
  Bottom Layer w20: Cen3.1@1590,3120 1660,3120 1710,3070 v2(1735,3070)
39: Cen2.1 M2.3 M3.10 Ren2.2 Rfccm3.2 | length 492.5
  Top Layer w8: v2(2215,3070) 2230,3085 M2.3@2230,3118
  Top Layer w10: Rfccm3.2@1649,3449.5 Rfccm3.2@1690,3449.5 ; Rfccm3.2@1670,3450 1670,3415 1700,3385 1723,3385 1750,3358 M3.10@1750,3311
  Bottom Layer w10: 2044,3119.5 2085,3119.5
  Bottom Layer w20: Cen2.1@2065,3120 2140,3120 2190,3070 v2(2215,3070)
40: Cbst3.2 Cen4.1 M3.8 M4.3 Ren4.2 | length 417.1
  Top Layer w10: v2(1255,3070) 1270,3085 M4.3@1270,3118 ; M3.8@1790,3311 1790,3420 Cbst3.2@1820,3450
  Bottom Layer w10: 1159,3119.5 1200,3119.5
  Bottom Layer w20: Cen4.1@1105,3120 1180,3120 1189,3120 1240,3070 v2(1255,3070)
41: Cen1.1 M1.3 Ren1.2 | length 266.8
  Top Layer w8: v2(2695,3070) 2710,3085 M1.3@2710,3118
  Bottom Layer w10: 2524,3119.5 2565,3119.5
  Bottom Layer w20: Cen1.1@2545,3120 2618,3120 2620,3118 ; 2620,3120 2670,3070 v2(2695,3070)
45: Ctao1.1 Ctao2.1 Ctao3.1 Ctao4.1 Ctsen.1 M1.11 M2.11 M3.11 M4.11 NC3.1 NC4.1 Rtsen.1 U1.33 U1.34 U1.40 | length 4809.4
  Top Layer w10: v1(1235,3360) 1251,3343 M4.11@1251,3311 ; v1(1715,3360) 1731,3343 M3.11@1731,3311 ; v1(2195,3360) 2211,3343 M2.11@2211,3311 ; v1(2675,3360) 2691,3343 M1.11@2691,3311 ; v2(3879,3305) 3879,3221 3941,3158 U1.40@3941,3144 ; U1.34@4059,3144 4059,3219 4115,3275 4115,3415 4345,3645 v5(4345,3705) ; U1.33@4079,3144 4079,3214 4140,3275 4140,3300 v5(4345,3505)
  Mid-Layer 5 w20: v1(1235,3360) 1235,3335 1265,3305 1695,3305 1715,3325 1715,3355 ; v1(1715,3360) 2103,3360 2123,3340 2175,3340 v1(2195,3360) 2585,3360 2610,3335 2650,3335 v1(2675,3360) v1(3275,3360)
  Bottom Layer w10: 1279.5,3296 1279.5,3337 ; 2228,3319.5 Ctao2.1@2261,3319.5 ; 2719.5,3299 2719.5,3340 ; 3430,3350 3510,3350 3584,3350 3630,3305 v2(3879,3305) ; 3489,3349.5 3530,3349.5
  Bottom Layer w20: v1(1235,3360) 1235,3330 1247,3317 1280,3317 ; 1715,3355 1715,3335 1730,3320 1760,3320 ; v1(2195,3360) 2195,3330 2205,3320 2245,3320 ; v1(2675,3360) 2675,3330 2685,3320 2720,3320 ; v1(3275,3360) 3284,3350 3430,3350
56: Ccomp2.2 Ccomp.2 Cref1.1 Cref2.1 Cref3.1 Cref4.1 Cref.1 M1.2 M2.2 M3.2 M4.2 Raddr.1 Rimax.1 Risum.1 Rmode.1 Rramp.1 Rusr.1 Rvboott.1 U1.13 | length 12362.3
  Top Layer w10: Cref4.1@1145,3110 1145,3055 1160,3040 v2(1190,3040) 1251,3101 M4.2@1251,3118 ; v2(1670,3040) 1731,3101 M3.2@1731,3118 ; v2(2150,3040) 2165,3040 2190,3065 2190,3080 2211,3101 M2.2@2211,3118 ; v2(2630,3040) 2650,3040 2660,3050 2660,3070 2691,3101 M1.2@2691,3118 ; 3829,2753.5 3870,2753.5 ; Ccomp2.2@3838.5,2809 Ccomp2.2@3838.5,2850 ; Ccomp2.2@3839,2830 Ccomp2.2@3840,2829 ; v2(3940,2855) 3980,2895 U1.13@3980,2915
  Top Layer w20: Ccomp2.2@3839,2830 3870,2830 3885,2814 3920,2814 3940,2834 v2(3940,2855) ; Ccomp2.2@3840,2829 3840,2796 3850,2786 3850,2754
  MidLayer2 w10: v2(1190,3040) 1325,3040 1530,2835 3805,2835 ; v2(1670,3040) 1805,3040 1970,2875 3195,2875 3295,2975 3805,2975 ; 2150,3045 v2(2150,3040) 2285,3040 2400,2925 3125,2925 3270,3070 3785,3070 ; v2(2630,3040) 3160,3040 3285,3165 3395,3165 3431,3129 v1(3726,3129)
  MidLayer2 w20: v1(3726,3129) 3785,3070 3805,3050 3805,2975 3805,2720 ; v2(3940,2855) 3805,2720 ; v1(4415,3385) 4415,2635 4365,2585 3860,2585 3805,2640 3805,2720
  Bottom Layer w10: Cref3.1@1509.5,3103 1509.5,3136 ; Cref2.1@1984.5,3103 1984.5,3136 ; Cref1.1@2449,3119.5 Cref1.1@2490,3119.5 ; 3709,3179.5 Rramp.1@3742,3179.5 ; 3724,3180 3725,3179 ; 3938.5,2774 3938.5,2815 ; Rimax.1@4337,3384.5 4370,3384.5 ; 4353.5,3129 4353.5,3170 ; 4353.5,3209 4353.5,3250 ; 4353.5,3284 4353.5,3325
  Bottom Layer w20: Cref3.1@1520,3120 1512,3112 1512,3082 1555,3040 v2(1670,3040) ; Cref2.1@1985,3120 1985,3080 2025,3040 v2(2150,3040) ; Cref1.1@2470,3120 2470,3080 2510,3040 v2(2630,3040) ; v1(3726,3129) 3726,3180 ; 3940,2795 v2(3940,2855) ; 4354,3075 4354,3150 4354,3230 4354,3305 4354,3385 v1(4415,3385)
62: Cout_1.1 Cout_2.1 Cout_3.1 Cout_4.1 Coutx_ch1_1.1 Coutx_ch1_2.1 Coutx_ch1_3.1 Coutx_ch1_4.1 Coutx_ch1_5.1 Coutx_ch1_6.1 Coutx_ch1_7.1 Coutx_ch1_8.1 Coutx_ch1_9.1 Coutx_ch1_10.1 Coutx_ch1_11.1 Coutx_ch1_12.1 Coutx_ch2_1.1 Coutx_ch2_2.1 Coutx_ch2_3.1 Coutx_ch2_4.1 Coutx_ch2_5.1 Coutx_ch2_6.1 Coutx_ch2_7.1 Coutx_ch2_8.1 Coutx_ch2_9.1 Coutx_ch2_10.1 Coutx_ch2_11.1 Coutx_ch2_12.1 L1.2 L2.2 L3.2 L4.2 Rsp.1 VOUT.1 | length 10407.9
  Top Layer w10: L3.2@1869.5,2568 L3.2@1869.5,2652 ; L2.2@2349.5,2568 L2.2@2349.5,2652 ; 2774,2610 L1.2@2885,2610 ; Coutx_ch1_1.1@3187,2185 3217,2155 3250,2155 v2(3255,2160)
  Top Layer w20: L4.2@1390,2610 1870,2610 2350,2610 2830,2610 3084,2610 3187,2508 3187,2185 1225,2185 1165,2125 1165,1695 1240,1620 1480,1620 1640,1460 v3(1640,1230)
  Bottom Layer w10: Cout_1.1@3109,2230 3109,2326 ; v2(3255,2160) 3265,2160 3300,2195
  Bottom Layer w20: 2985,2690 1130,2690 1100,2660 1100,2230 1160,2170 3075,2170 3110,2205 Cout_1.1@3110,2278
  other v1: 2335,1210 2335,1315 2335,1420 2335,1525 1435,1625 1540,1625 1645,1625 1760,1625 1870,1625 1980,1625 2085,1625 2190,1625 2295,1625 1295,2375 1365,2375 1440,2375 1780,2375 1850,2375 1925,2375 2270,2375 2340,2375 2415,2375 2755,2375 2825,2375 2900,2375 1168,2555 1600,2555 1665,2555 2085,2555 2145,2555 2555,2555 3035,2555 2625,2559 1168,2588 1600,2590 1665,2590 2085,2590 2145,2590 2555,2590 3035,2590 2625,2593 1168,2624 1600,2625 1665,2625 2085,2625 2145,2625 2555,2625 3035,2625 2625,2626 1075,2648 1075,2685
65: Ccomp.1 Rcomp.1 | length 174.7
  Top Layer w10: 3774.5,2678 Rcomp.1@3774.5,2711 ; 3775,2695 3850,2695 3860,2695 ; 3790,2700 3792,2697 ; 3829,2694.5 3870,2694.5 ; 3865,2695 3860,2695 ; 3865,2700 3860,2695
69: C3v3.1 Cbp3.1 Cbst4.2 M4.8 M4.10 Ren1.1 Ren2.1 Ren3.1 Ren4.1 Rfccm4.2 Rnc1.1 Rnc2.1 Rvr_fault.1 Rvr_hot.1 Rvr_rdy.1 U1.14 U1.21 U1.23 | length 1613.1
  Top Layer w10: Rfccm4.2@1179.5,3433 1179.5,3466 ; Rfccm4.2@1180,3450 1180,3420 1210,3390 1250,3390 1270,3369 M4.10@1270,3311 ; M4.8@1310,3311 1310,3430 Cbst4.2@1335,3455 ; Cbst4.2@1334.5,3438 1334.5,3471 ; v2(3975,2860) 3975,2866 4000,2891 U1.14@4000,2915 ; 3989.5,2797 3989.5,2830 ; U1.21@4144,2941 4161,2941 v2(4180,2960) 4159,2980 U1.23@4144,2980
  Top Layer w15: v2(3975,2860) 3990,2845 Cbp3.1@3990,2814
  Top Layer w20: v1(3485,2565) Rnc2.1@3485,2615 ; v1(3565,2565) Rnc1.1@3565,2615 ; v2(4180,2960) 4195,2945 4320,2945 4370,2895 v2(4370,2860)
  Bottom Layer w10: 1159,3178.5 1200,3178.5 ; Ren3.1@1659.5,3162 1659.5,3195 ; Rvr_rdy.1@4214.5,2743 4214.5,2776 ; Rvr_hot.1@4289.5,2743 4289.5,2776 ; 4369.5,2802 4369.5,2835 ; Rvr_fault.1@4618.5,3074 Rvr_fault.1@4618.5,3115
  Bottom Layer w20: 1180,3179 v1(1180,3230) ; 1660,3179 v1(1660,3230) ; 2140,3179 v1(2140,3230) ; 2620,3179 v1(2620,3230) ; v1(4215,2710) Rvr_rdy.1@4215,2760 ; v1(4290,2715) Rvr_hot.1@4290,2760 ; C3v3.1@4370,2819 v2(4370,2860) ; Rvr_fault.1@4621,3095 v1(4670,3095)
74: Csnub3.2 Rsnub3.1 | length 152
  Top Layer w10: 1964,3109.5 2005,3109.5 ; Csnub3.2@1984.5,3019 1984.5,3060
  Top Layer w30: Csnub3.2@1985,3040 1985,3110
75: Csnub2.2 Rsnub2.1 | length 111
  Top Layer w10: Csnub2.2@2464.5,3019 2464.5,3060
  Top Layer w30: Csnub2.2@2465,3040 2465,3110
76: Csnub4.2 Rsnub4.1 | length 144
  Top Layer w10: Csnub4.2@1504.5,3019 1504.5,3060 ; 1504.5,3093 Rsnub4.1@1504.5,3126
  Top Layer w30: Csnub4.2@1505,3040 1505,3110
77: Csnub1.2 Rsnub1.1 | length 144
  Top Layer w10: Csnub1.2@2954.5,3019 2954.5,3060 ; 2954.5,3093 Rsnub1.1@2954.5,3126
  Top Layer w25: Csnub1.2@2955,3040 2955,3110
78: Cbst3.1 Rbst3.1 | length 109
  Top Layer w10: 1724,3508.5 1765,3508.5
  Top Layer w20: 1745,3509 Cbst3.1@1813,3509
79: Cbst2.1 Rbst2.1 | length 154
  Top Layer w10: 2204,3508.5 2245,3508.5 ; 2294.5,3492 2294.5,3525
  Top Layer w20: 2225,3509 Cbst2.1@2295,3509 ; Cbst2.1@2295,3511 Cbst2.1@2305,3511
80: Cbst4.1 Rbst4.1 | length 146
  Top Layer w10: Rbst4.1@1254.5,3497 1254.5,3530 ; Cbst4.1@1334.5,3497 1334.5,3530
  Top Layer w20: 1255,3514 Cbst4.1@1335,3514
81: Cbst1.1 Rbst1.1 | length 103.8
  Top Layer w10: Rbst1.1@2704.5,3492 2704.5,3525
  Top Layer w20: 2705,3509 2773,3509 Cbst1.1@2775,3511
84: Csnub1.1 L1.1 M1.6 | length 622.5
  Top Layer w10: 2774,2929 L1.1@2885,2929 ; L1.1@2830,2929 2830,3040 2868,3078 M1.6@2868,3118 ; Csnub1.1@3013.5,3019 3013.5,3060
  Top Layer w30: L1.1@2830,2929 2964,2929 3014,2979 Csnub1.1@3014,3040
85: Csnub2.1 L2.1 M2.6 | length 594.8
  Top Layer w10: L2.1@2349.5,2887 L2.1@2349.5,2971 ; L2.1@2350,2929 2350,3045 2388,3083 M2.6@2388,3118 ; Csnub2.1@2523.5,3019 2523.5,3060
  Top Layer w30: L2.1@2350,2929 2350,2930 2490,2930 2524,2964 Csnub2.1@2524,3040
86: Csnub3.1 L3.1 M3.6 | length 588.4
  Top Layer w10: L3.1@1869.5,2887 L3.1@1869.5,2971 ; L3.1@1870,2929 1870,3050 1908,3088 M3.6@1908,3118 ; Csnub3.1@2043.5,3019 2043.5,3060
  Top Layer w30: L3.1@1870,2929 1999,2929 2044,2974 Csnub3.1@2044,3040
87: Csnub4.1 L4.1 M4.6 | length 507.3
  Top Layer w10: L4.1@1390,2929 1390,3050 1428,3088 M4.6@1428,3118 ; Csnub4.1@1563.5,3019 1563.5,3060
  Top Layer w30: L4.1@1390,2929 1524,2929 1564,2969 Csnub4.1@1564,3040
95: Cbst2.2 M2.8 | length 182.4
  Top Layer w10: M2.8@2270,3311 2270,3425 Cbst2.2@2295,3450 ; 2294.5,3433 2294.5,3466
107: Rvr_rdy.2 U1.18 | length 238.4
  Top Layer w10: U1.18@4079,2915 4079,2895 4100,2875 4155,2875 v2(4166,2864)
  Bottom Layer w10: v2(4166,2864) 4201,2864 4215,2850 Rvr_rdy.2@4215,2819 ; Rvr_rdy.2@4214.5,2802 Rvr_rdy.2@4214.5,2835
108: Rvr_fault.2 U1.27 | length 479.1
  Top Layer w10: U1.27@4144,3059 4215,3059 4225,3050 4385,3050 4430,3095 v1(4515,3095)
  Bottom Layer w10: v1(4515,3095) Rvr_fault.2@4560,3095 ; Rvr_fault.2@4559.5,3074 Rvr_fault.2@4559.5,3115
109: Risum.2 U1.12 | length 203.3
  Top Layer w10: v2(3905,2865) 3915,2875 3930,2875 3961,2906 U1.12@3961,2915
  Bottom Layer w10: 3879.5,2774 3879.5,2815 ; 3880,2795 3880,2840 v2(3905,2865)
110: Rfccm1.1 Rfccm2.1 Rfccm3.1 Rfccm4.1 Rnvm.1 U1.39 | length 3768.3
  Top Layer w10: Rfccm4.1@1179.5,3492 Rfccm4.1@1179.5,3525 ; Rfccm4.1@1180,3509 v1(1180,3565) ; Rfccm3.1@1649,3508.5 Rfccm3.1@1690,3508.5 ; Rfccm3.1@1670,3509 v1(1670,3565) ; Rfccm2.1@2134,3508.5 Rfccm2.1@2175,3508.5 ; Rfccm2.1@2155,3509 v1(2155,3565) ; Rfccm1.1@2634.5,3492 Rfccm1.1@2634.5,3525 ; Rfccm1.1@2635,3509 v1(2635,3565) ; U1.39@3961,3144 3961,3178 3953,3186 3953,3338 v2(4025,3410)
  Bottom Layer w10: v1(1180,3565) v1(1670,3565) v1(2155,3565) v1(2635,3565) 3530,3565 3685,3410 v2(4025,3410) 4090,3475 4145,3475 ; 4144.5,3454 4144.5,3495
115: Rsp.2 U1.9 | length 1267.3
  Top Layer w10: v2(3540,2160) 3545,2155 3585,2155 3640,2210 3640,2814 3786,2961 U1.9@3915,2961
  Bottom Layer w10: 3359,2195 3364,2190 3364,2185 3395,2155 3535,2155 v2(3540,2160)
116: Rsn.2 U1.10 | length 1300
  Top Layer w10: v2(3540,2130) 3545,2135 3593,2135 3660,2201 3660,2806 3795,2941 U1.10@3915,2941
  Bottom Layer w10: Rsn.2@3342,2094.5 3375,2094.5 ; 3359,2095 3364,2100 3364,2104 3395,2135 3535,2135 v2(3540,2130)
118: Rvr_hot.2 U1.19 | length 293.5
  Top Layer w10: U1.19@4098,2915 4098,2901 4110,2890 4193,2890 v2(4195,2888)
  Bottom Layer w10: v2(4195,2888) 4256,2888 4290,2855 Rvr_hot.2@4290,2819 ; Rvr_hot.2@4289.5,2802 Rvr_hot.2@4289.5,2835
123: M4.12 U1.35 | length 3571.1
  Top Layer w10: v1(1195,3370) 1195,3325 1208,3311 M4.12@1231,3311 ; U1.35@4039,3144 4039,3224 4046,3231 v2(4046,3266)
  MidLayer2 w10: v1(1195,3370) 1220,3395 1220,3590 1275,3645 2936,3645 2971,3610 3485,3610 3590,3505 3590,3295 3619,3266 v2(4046,3266)
124: M3.12 U1.36 | length 2995.6
  Top Layer w10: v1(1675,3370) 1675,3330 1693,3311 M3.12@1711,3311 ; U1.36@4020,3144 4020,3185 4024,3189 v2(4024,3244)
  MidLayer2 w10: v1(1675,3370) 1675,3506 1788,3620 2930,3620 2960,3590 3470,3590 3570,3490 3570,3285 3611,3244 v2(4024,3244)
  Mid-Layer 5 w10: 4019,3241 4020,3240
125: M2.12 U1.37 | length 2448.1
  Top Layer w10: v1(2155,3370) 2155,3330 2173,3311 M2.12@2191,3311 ; U1.37@4000,3144 4000,3190 4001,3191 4001,3219 4000,3220 ; 4002,3220 v2(4002,3222)
  MidLayer2 w10: v1(2155,3370) 2155,3490 2260,3595 2925,3595 2950,3570 3460,3570 3550,3480 3550,3275 3603,3222 v2(4002,3222)
126: M1.12 U1.38 | length 1895.1
  Top Layer w10: v1(2635,3370) 2635,3330 2653,3311 M1.12@2671,3311 ; U1.38@3980,3144 3980,3199 v2(3980,3200)
  MidLayer2 w10: v1(2635,3370) 2635,3495 2690,3550 3450,3550 3530,3470 3530,3270 3600,3200 v2(3980,3200)
127: U1.26 Vsda.1 | length 773.7
  Top Layer w10: U1.26@4144,3039 4198,3039 4213,3025 4700,3025 v3(4850,3175)
128: U1.24 Vscl.1 | length 798.9
  Top Layer w10: U1.24@4144,3000 4179,3000 4200,2980 4645,2980 v3(4850,2775)
129: U1.25 Valert.1 | length 724.4
  Top Layer w10: U1.25@4144,3020 4189,3020 4205,3005 4685,3005 4715,2975 v3(4850,2975)
134: M4.1 U1.6 | length 3330.9
  Top Layer w10: v2(1190,3070) 1190,3100 1208,3118 M4.1@1231,3118 ; v1(3375,2725) 3415,2725 3710,3020 U1.6@3915,3020
  MidLayer2 w10: v2(1190,3070) 1155,3070 1130,3045 1130,2802 1167,2765 3280,2765 3320,2725 v1(3375,2725)
135: M3.1 U1.5 | length 2692.5
  Top Layer w10: v2(1670,3070) 1670,3105 1683,3118 M3.1@1711,3118 ; v1(3375,2920) 3580,2920 3699,3039 U1.5@3915,3039
  MidLayer2 w10: v2(1670,3070) 1640,3070 1615,3045 1615,2890 1650,2855 3260,2855 3325,2920 v1(3375,2920)
136: M2.1 U1.4 | length 2160
  Top Layer w10: v2(2150,3070) 2150,3095 2173,3118 M2.1@2191,3118 ; v1(3375,3025) 3660,3025 3694,3059 U1.4@3915,3059
  MidLayer2 w10: v2(2150,3070) 2120,3070 2095,3045 2095,2920 2115,2900 3144,2900 3269,3025 v1(3375,3025)
137: M1.1 U1.3 | length 1650.1
  Top Layer w10: v2(2630,3070) 2630,3095 2653,3118 M1.1@2671,3118 ; v1(3375,3125) 3630,3125 3675,3079 U1.3@3915,3079
  MidLayer2 w10: v2(2630,3070) 2600,3070 2575,3045 2575,2980 2605,2950 3110,2950 3285,3125 v1(3375,3125)
140: M2.9 Rbst2.2 | length 190.1
  Top Layer w10: 2204,3449.5 2245,3449.5 ; 2225,3450 2250,3424 M2.9@2250,3311
144: M1.9 Rbst1.2 | length 182.1
  Top Layer w10: 2704.5,3433 Rbst1.2@2704.5,3466 ; 2705,3450 2730,3424 M1.9@2730,3311
145: Cbst1.2 M1.8 | length 149.4
  Top Layer w10: M1.8@2750,3311 2750,3425 Cbst1.2@2775,3450
146: M1.10 Rfccm1.2 | length 223.3
  Top Layer w10: Rfccm1.2@2634.5,3433 2634.5,3466 ; Rfccm1.2@2635,3450 2635,3415 2660,3389 2695,3389 2710,3374 M1.10@2710,3311
148: M2.10 Rfccm2.2 | length 225.4
  Top Layer w10: Rfccm2.2@2134,3449.5 Rfccm2.2@2175,3449.5 ; Rfccm2.2@2155,3450 2155,3410 2182,3383 2207,3383 2230,3359 M2.10@2230,3311
150: M4.9 Rbst4.2 | length 191.2
  Top Layer w10: 1254.5,3438 Rbst4.2@1254.5,3471 ; 1255,3455 1290,3419 M4.9@1290,3311
155: M3.9 Rbst3.2 | length 190.1
  Top Layer w10: 1724,3449.5 1765,3449.5 ; 1745,3450 1770,3424 M3.9@1770,3311
158: Rnc2.2 U1.7 | length 618.3
  Top Layer w10: Rnc2.2@3485,2674 3485,2765 3720,3000 U1.7@3915,3000
159: Rnc1.2 U1.8 | length 562.3
  Top Layer w10: Rnc1.2@3565,2674 3565,2820 3725,2980 U1.8@3915,2980

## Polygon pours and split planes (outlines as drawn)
69 on Top Layer " " (solid, pour order 16): 3537,2591 3537,2638 3592,2638 3592,2591
159 on Top Layer " " (solid, pour order 17): 3537,2650 3537,2697 3592,2697 3592,2650
145 on Top Layer " " (solid, pour order 18): 2747,3426 2747,3473 2802,3473 2802,3426
81 on Top Layer " " (solid, pour order 19): 2747,3485 2747,3532 2802,3532 2802,3485
40 on Top Layer " " (solid, pour order 20): 1792,3426 1792,3473 1847,3473 1847,3426
78 on Top Layer " " (solid, pour order 21): 1792,3485 1792,3532 1847,3532 1847,3485
1 on Top Layer " " (solid, pour order 22): 2513,3292 2513,3367 2585,3367 2585,3292
56 on Top Layer " " (solid, pour order 23): 1117,3086 1117,3133 1172,3133 1172,3086
116 on Top Layer " " (solid, pour order 24): 3908,2936 3908,2945 3918,2945 3918,2936
115 on Top Layer " " (solid, pour order 25): 3908,2956 3908,2965 3918,2965 3918,2956
30 on Top Layer " " (solid, pour order 26): 3936,2908 3936,2918 3945,2918 3945,2908
159 on Top Layer " " (solid, pour order 27): 3908,2976 3908,2985 3918,2985 3918,2976
158 on Top Layer " " (solid, pour order 28): 3908,2995 3908,3004 3918,3004 3918,2995
109 on Top Layer " " (solid, pour order 29): 3956,2908 3956,2918 3965,2918 3965,2908
69 on Top Layer " " (solid, pour order 30): 3995,2908 3995,2918 4004,2918 4004,2908
56 on Top Layer " " (solid, pour order 31): 3976,2908 3976,2918 3985,2918 3985,2908
136 on Top Layer " " (solid, pour order 32): 3908,3055 3908,3064 3918,3064 3918,3055
137 on Top Layer " " (solid, pour order 33): 3908,3074 3908,3083 3918,3083 3918,3074
134 on Top Layer " " (solid, pour order 34): 3908,3015 3908,3024 3918,3024 3918,3015
135 on Top Layer " " (solid, pour order 35): 3908,3035 3908,3044 3918,3044 3918,3035
31 on Top Layer " " (solid, pour order 36): 3908,3093 3908,3102 3918,3102 3918,3093
2 on Top Layer " " (solid, pour order 37): 3908,3114 3908,3123 3918,3123 3918,3114
45 on Top Layer " " (solid, pour order 38): 3936,3136 3936,3146 3945,3146 3945,3136
125 on Top Layer " " (solid, pour order 39): 3995,3136 3995,3146 4004,3146 4004,3136
110 on Top Layer " " (solid, pour order 40): 3956,3136 3956,3146 3965,3146 3965,3136
126 on Top Layer " " (solid, pour order 41): 3976,3136 3976,3146 3985,3146 3985,3136
22 on Top Layer " " (solid, pour order 42): 4035,2908 4035,2918 4044,2918 4044,2908
23 on Top Layer " " (solid, pour order 43): 4015,2908 4015,2918 4024,2918 4024,2908
118 on Top Layer " " (solid, pour order 44): 4093,2908 4093,2918 4102,2918 4102,2908
107 on Top Layer " " (solid, pour order 45): 4074,2908 4074,2918 4083,2918 4083,2908
69 on Top Layer " " (solid, pour order 46): 4136,2936 4136,2945 4146,2945 4146,2936
69 on Top Layer " " (solid, pour order 47): 4136,2976 4136,2985 4146,2985 4146,2976
128 on Top Layer " " (solid, pour order 48): 4136,2995 4136,3004 4146,3004 4146,2995
123 on Top Layer " " (solid, pour order 49): 4035,3136 4035,3146 4044,3146 4044,3136
45 on Top Layer " " (solid, pour order 50): 4055,3136 4055,3146 4064,3146 4064,3136
124 on Top Layer " " (solid, pour order 51): 4015,3136 4015,3146 4024,3146 4024,3136
5 on Top Layer " " (solid, pour order 52): 4093,3136 4093,3146 4102,3146 4102,3136
45 on Top Layer " " (solid, pour order 53): 4074,3136 4074,3146 4083,3146 4083,3136
108 on Top Layer " " (solid, pour order 54): 4136,3055 4136,3064 4146,3064 4146,3055
10 on Top Layer " " (solid, pour order 55): 4136,3074 4136,3083 4146,3083 4146,3074
129 on Top Layer " " (solid, pour order 56): 4136,3015 4136,3024 4146,3024 4146,3015
127 on Top Layer " " (solid, pour order 57): 4136,3035 4136,3044 4146,3044 4146,3035
7 on Top Layer " " (solid, pour order 58): 4136,3114 4136,3123 4146,3123 4146,3114
6 on Top Layer " " (solid, pour order 59): 4114,3136 4114,3146 4123,3146 4123,3136
9 on Top Layer " " (solid, pour order 60): 4136,3093 4136,3102 4146,3102 4146,3093
62 on Top Layer " " (solid, pour order 61): 3150,2152 3150,2227 3222,2227 3222,2152
62 on Top Layer " " (solid, pour order 62): 2425,1050 2425,1675 1350,1675 1350,2150 3170,2150 3170,2175 3250,2175 3250,2750 1050,2750 1050,1050
1 on Top Layer " " (solid, pour order 63): 3175,3300 3175,3625 4150,3625 4150,4450 3825,4450 3825,4025 1325,4025 1325,3575 1375,3575 1375,3400 1325,3400 1325,3300 1650,3300 1650,3400 1625,3400 1625,3575 1875,3575 1875,3400 1810,3400 1810,3300 2100,3300 2100,3575 2350,3575 2350,3400 2290,3400 2290,3300 2600,3300 2600,3575 2825,3575 2825,3400 2775,3400 2775,3300
87 on Top Layer " " (solid, pour order 64): 1175,2775 1175,3000 1325,3000 1325,3125 1450,3125 1450,3000 1550,3000 1600,3000 1600,2775
86 on Top Layer " " (solid, pour order 65): 1650,3000 1650,2775 2075,2775 2075,3000 1925,3000 1925,3125 1805,3125 1805,3000
85 on Top Layer " " (solid, pour order 66): 2575,3000 2575,2775 2125,2775 2125,3000 2300,3000 2300,3125 2400,3125 2400,3000
84 on Top Layer " " (solid, pour order 67): 2625,2775 2625,3000 2775,3000 2775,3125 2875,3125 2875,3000 3050,3000 3050,2775
24 on Top Layer " " (solid, pour order 68): 4175,4450 4350,4450 4350,4215 4175,4215
0 on Top Layer " " (solid, pour order 83): 2513,3202 2513,3277 2585,3277 2585,3202
0 on Top Layer " " (solid, pour order 84): 1117,3145 1117,3192 1172,3192 1172,3145
0 on Top Layer " " (solid, pour order 85): 3150,2062 3150,2137 3222,2137 3222,2062
0 on Top Layer " " (solid, pour order 86): 3800,4450 3800,4050 1300,4050 1300,3575 1125,3575 1125,3275 3200,3275 3200,3600 4175,3600 4175,4200 4375,4200 4375,4450 4950,4450 4950,1050 2450,1050 2450,1700 1375,1700 1375,2135 3170,2135 3170,2110 3275,2110 3275,2775 3075,2775 3075,3150 1100,3150 1100,3000 1150,3000 1150,2775 1050,2775 1050,4450
62 on Bottom Layer " " (solid, pour order 0): 2929,2650 2929,2730 3039,2730 3039,2650
31 on Bottom Layer " " (solid, pour order 1): 3836,3072 3836,3127 3883,3127 3883,3072
45 on Bottom Layer " " (solid, pour order 2): 3402,3326 3402,3373 3457,3373 3457,3326
22 on Bottom Layer " " (solid, pour order 3): 4112,2795 4112,2842 4167,2842 4167,2795
45 on Bottom Layer " " (solid, pour order 4): 1736,3292 1736,3347 1783,3347 1783,3292
40 on Bottom Layer " " (solid, pour order 5): 1077,3096 1077,3143 1132,3143 1132,3096
56 on Bottom Layer " " (solid, pour order 6): 4330,3047 4330,3102 4377,3102 4377,3047
10 on Bottom Layer " " (solid, pour order 7): 4271,3047 4271,3102 4318,3102 4318,3047
41 on Bottom Layer " " (solid, pour order 8): 2592,3096 2592,3143 2647,3143 2647,3096
69 on Bottom Layer " " (solid, pour order 9): 2592,3155 2592,3202 2647,3202 2647,3155
23 on Bottom Layer " " (solid, pour order 10): 4437,3995 4437,4054 4488,4054 4488,3995
24 on Bottom Layer " " (solid, pour order 11): 4370,3995 4370,4054 4421,4054 4421,3995
6 on Bottom Layer " " (solid, pour order 12): 4180,3277 4180,3332 4227,3332 4227,3277
5 on Bottom Layer " " (solid, pour order 13): 4180,3357 4180,3412 4227,3412 4227,3357
115 on Bottom Layer " " (solid, pour order 14): 3335,2167 3335,2222 3382,2222 3382,2167
62 on Bottom Layer " " (solid, pour order 15): 3276,2167 3276,2222 3323,2222 3323,2167
62 on Bottom Layer " " (solid, pour order 75): 1050,2725 1050,1050 2425,1050 2425,1675 1350,1675 1350,2150 3235,2150 3235,2725
1 on Bottom Layer " " (solid, pour order 76): 1325,3375 1400,3375 1400,3325 1650,3325 1650,3375 1875,3375 1875,3325 2125,3325 2125,3375 2350,3375 2350,3325 2600,3325 2600,3375 2825,3375 2825,3325 3175,3325 3175,3650 4075,3650 4075,4450 3825,4450 3825,4000 1325,4000
0 on Bottom Layer " " (solid, pour order 80): 1568,3237 1568,3312 1640,3312 1640,3237
0 on Bottom Layer " " (solid, pour order 81): 2048,3237 2048,3312 2120,3312 2120,3237
0 on Bottom Layer " " (solid, pour order 82): 1795,3292 1795,3347 1842,3347 1842,3292
0 on Bottom Layer " " (solid, pour order 92): 3800,4450 3800,4025 1300,4025 1300,3375 1250,3375 1250,3280 1320,3280 1320,3350 1375,3350 1375,3310 1695,3310 1695,3275 1800,3275 1800,3350 1850,3350 1850,3310 2175,3310 2175,3275 2275,3275 2275,3350 2325,3350 2325,3310 2660,3310 2660,3280 2750,3280 2750,3350 2800,3350 2800,3310 3200,3310 3200,3625 4100,3625 4100,4450 4950,4450 4950,1050 2475,1050 2450,1050 2450,1700 1375,1700 1375,2125 3125,2125 3235,2125 3235,2050 3400,2050 3400,2100 3575,2100 3575,2200 3400,2200 3400,2250 3275,2250 3275,2750 1050,2750 1050,4450
62 on MidLayer2 " " (solid, pour order 69): 1050,2700 3250,2700 3250,2175 4950,2175 4950,1050 1050,1050
56 on MidLayer2 " " (solid, pour order 70): 1050,3100 1050,2725 3275,2725 3275,2200 4950,2200 4950,3625 4100,3625 4100,3150 3425,3150 3425,3225 3200,3225 3200,3100
1 on MidLayer2 " " (solid, pour order 71): 3825,4450 3825,4025 1325,4025 1325,3300 3150,3300 3150,3650 4950,3650 4950,4450
62 on Mid-Layer 3 " " (solid, pour order 72): 1050,2750 1050,1050 2425,1050 2425,1675 1350,1675 1350,2150 3250,2150 3250,2750
1 on Mid-Layer 4 " " (solid, pour order 73): 1350,4000 3825,4000 3825,4450 4950,4450 4950,3325 1350,3325
69 on Mid-Layer 4 " " (solid, pour order 74): 4950,3300 1150,3300 1150,3125 3425,3125 3425,2225 4950,2225
1 on Mid-Layer 5 " " (solid, pour order 77): 1325,4000 3825,4000 3825,4450 4075,4450 4075,3650 3150,3650 3150,3400 1325,3400
24 on Mid-Layer 5 " " (solid, pour order 78): 4100,4450 4100,3625 3175,3625 3175,3125 1050,3125 1050,2950 3475,2950 3475,3300 4450,3300 4450,4450
62 on Mid-Layer 5 " " (solid, pour order 79): 1050,2925 3475,2925 3475,1050 1050,1050
0 on MidLayer2 " " (solid, pour order 87): 3800,4450 1050,4450 1050,3125 3175,3125 3175,3250 3450,3250 3450,3175 4075,3175 4075,3625 3175,3625 3175,3275 1300,3275 1300,4050 3800,4050
0 on Mid-Layer 3 " " (solid, pour order 88): 1050,2775 3275,2775 3275,2125 1375,2125 1375,1700 2450,1700 2450,1050 4950,1050 4950,4450 1500,4450 1050,4450
0 on MidLayer1 " " (solid, pour order 89): 1050,4450 4950,4450 4950,1050 1050,1050
0 on Mid-Layer 6 " " (solid, pour order 90): 1050,4450 4950,4450 4950,1050 1050,1050
0 on Mid-Layer 4 " " (solid, pour order 91): 3800,4450 1050,4450 1050,1050 4950,1050 4950,2200 3400,2200 3400,3100 1125,3100 1125,3325 1325,3325 1325,4025 3800,4025
0 on Mid-Layer 5 " " (solid, pour order 93): 1050,4450 3800,4450 3800,4025 1300,4025 1300,3375 3150,3375 3150,3150 1050,3150
0 on Mid-Layer 5 " " (solid, pour order 94): 4475,4450 4950,4450 4950,1050 3500,1050 3500,3275 4475,3275

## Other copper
Multi-Layer:
  the board outline again, w1

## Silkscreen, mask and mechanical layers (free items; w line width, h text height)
Top Overlay:
  text "Cin" at 3550,3975 h50
  text "Coutx_ch1" at 3112,2245 h50
  text "Design Rules:" at 3470,1185 h30
  text "Min Clearance: 10mil" at 3850,1180 h30
  text "Min Track Width: 10mil" at 3850,1130 h30
Bottom Overlay:
  text "Coutx_ch2" at 2960,2865 h50 r270
  text "Cout" at 3180,2400 h50 r180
